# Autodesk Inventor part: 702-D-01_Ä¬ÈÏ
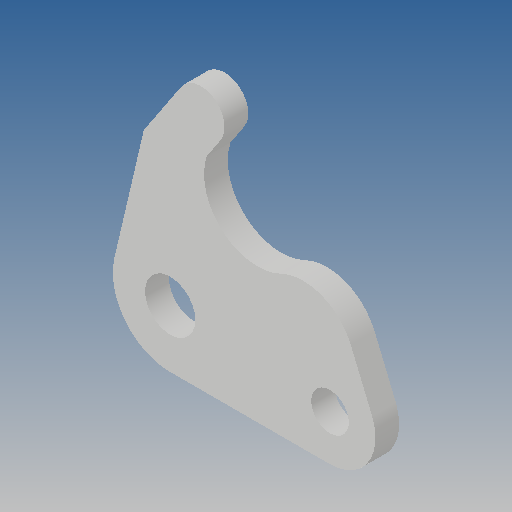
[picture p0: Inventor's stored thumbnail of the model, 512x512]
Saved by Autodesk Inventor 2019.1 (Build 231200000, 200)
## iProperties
Created: 2010-06
Part Number: 702-D-01_Ä¬ÈÏ
Material: Ogólny
Document SubType Name: Modeling
Designer: CADENGINEERING4
Density: 1 g/cm^3
Appearance: Domyślna
Author: CADENGINEERING4
Revision Number: ÈÎºÎ
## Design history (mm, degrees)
feature "NONE"
node "Bryła1"
